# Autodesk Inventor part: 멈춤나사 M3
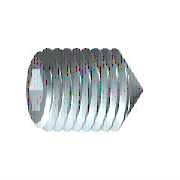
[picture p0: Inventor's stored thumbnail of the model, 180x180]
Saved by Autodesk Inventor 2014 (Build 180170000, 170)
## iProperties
IsCustomPart: 1
Created: 2012-02
Part Number: 멈춤나사 M3
Material: 강철, 연강
Description: 6각 소켓 머리 없는 멈춤 나사
Document SubType Name: Modeling
Standard: KS B 1028
Designer: test
Standards Organization: KS
Language: ko-KR
Size Designation: 원추점 M3x8
Categories: <MemberInstance><Categories><Category DisplayName="조임쇠" InternalName="e4da775c-781d-43d5-af7c-5136215cf5a6" Mnemonic="FSTN"><Category DisplayName="볼트" InternalN
Density: 1 g/cm^3
Appearance: Steel
Author: test
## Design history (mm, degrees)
sketch "스케치1"
  geometry: L1 (0, 0)-(5.5, 0); L2 (8, 0.866)-(8, 1.5); L3 (8, 1.5)-(0, 1.5); L4 (8, 0.866)-(6, 0.866); L5 (6, 0.866)-(5.5, 0); L6 (0, -0.3)-(0, 1.8) reference; L7 (0, 1.5)-(0, 0)
  constraints: 13 end point, 3 parallel, 1 collinear, 1 perpendicular, 1 point on line
  dimensions: "d0" = 2 distance of L2.start L4.end (= INTI); "d1" = 60 deg angle of L5 L1; "d2" = 3 diameter of L3 L1 (= NND); "d3" = 1.73205 diameter of L4 L1 (= 1.1547 x SW); "d5" = 8 distance from line of L2 L3.end (= NLG)
revolve "본체" sketch "스케치1" stored, may be unused: angle "d6" = 90 deg
sketch "스케치2"
  geometry: L1 (-0.433, 0.75)-(0.433, 0.75); L2 (0.433, 0.75)-(0.866, 0); L3 (0.866, 0)-(0.433, -0.75); L4 (0.433, -0.75)-(-0.433, -0.75); L5 (-0.433, -0.75)-(-0.866, 0); L6 (-0.866, 0)-(-0.433, 0.75); 3 further points
  constraints: 12 end point, 1 coincident, 1 horizontal, 13 other
extrude "슬롯" join sketch "스케치2" taper "d7" = 0 deg; stored distance "d21" = 10
workaxis "Work Axis1"
workplane "Work Plane1"
sketch "스케치4"
  geometry: L1 (0, 0.15)-(-1.35, 1.5) reference; L2 (0, -0.15)-(-1.35, -1.5) reference; L3 (-1.35, -1.5)-(0.15, 0); L4 (-1.35, 1.5)-(0.15, 0); 2 further points
  constraints: 4 end point, 1 coincident, 1 collinear, 1 horizontal alignment
workpoint "Work Point1"
body "Solid1"
feature "스레드" dims "d12" = 8 (= NLG), "d13" = 0
chamfer "모따기1" distance "d8" = 1.35 (computed from NND, SPD, FAWI); stored, may be unused: angle "d9" = 45 deg (= FAWI), second distance "d34" = 1.35 (computed from NND, SPD, FAWI)
chamfer "모따기2" distance "d10" = 0.30673 (= -0.5 x GD1 + 0.5 x NND); stored, may be unused: angle "d11" = 45 deg (= FAWI), second distance "d35" = 0.30673 (= -0.5 x GD1 + 0.5 x NND)
other parameters: "NND" = 3 [user parameter; used in 5 equation terms], "NLG" = 8 [user parameter; used in 2 equation terms], "INTI" = 2 [user parameter; used in 1 equation term], "FAWI" = 45 deg [user parameter; used in 4 equation terms], "SW" = 1.5 [user parameter; used in 2 equation terms], "GD1" = 2.38655 (= THREADDIA - 1.2269 x PTC) [user parameter; used in 2 equation terms], "d4" = 0, "FAWI1" = 45 deg [user parameter], "SPD" = 0.3 [user parameter; used in 2 equation terms], "d36" = 0, "d37" = 0, "GUL" = 0.30673 (= 0.61345 x PTC) [user parameter], "TOA" = 30 deg [user parameter], "THREADDIA" = 3 [user parameter; used in 1 equation term], "PTC" = 0.5 [user parameter; used in 4 equation terms], "GAL" = 0.30673 (= 0.61345 x PTC) [user parameter], "E0" = 1.7325 (= 1.155 x SW) [user parameter]
